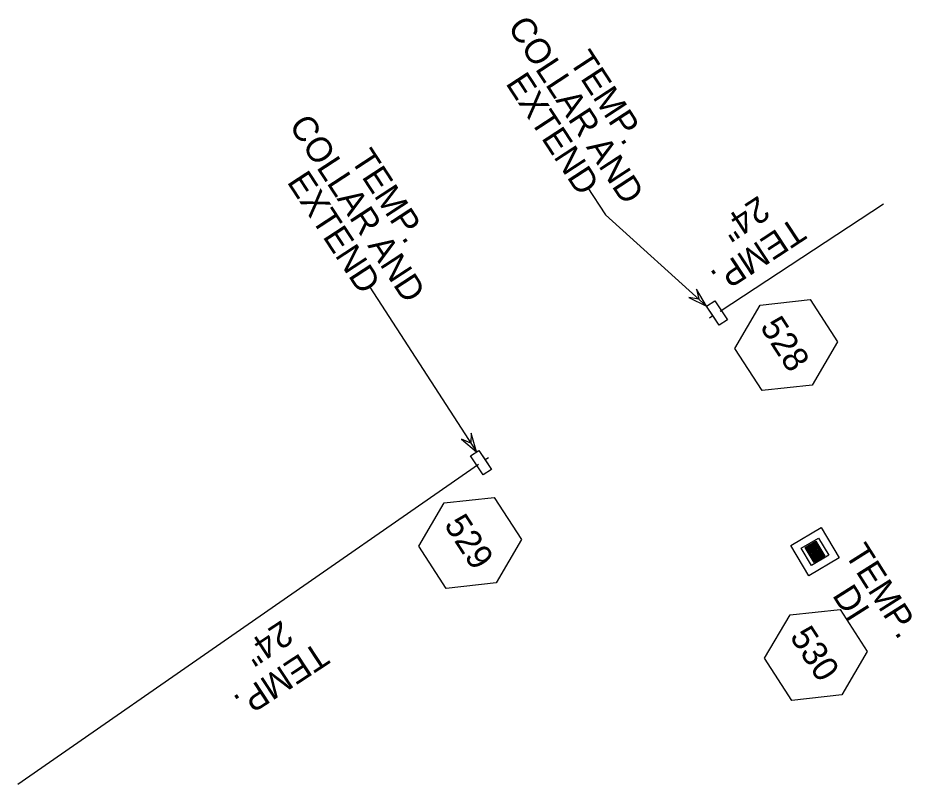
# Model space of a CAD drawing. Extents: x 2009474 to 2011404, y 538919 to 548212.
# Drawn here: x 2009473.8 to 2009651.7, y 548059.9 to 548212.4 of the extents above; entities that cross this region are included whole.
import ezdxf

# ---------------------------------------------------------------- set-up
doc = ezdxf.new("R2010")
doc.units = 0
for name, color, linetype in [('Prop Drainage Structure Box Number Symbol CELL', 7, 'Continuous'), ('Prop Drainage Structure Drop Inlet Grate 840 16 CELL', 7, 'Continuous'), ('Prop Drainage Structure Drop Inlet Grate 840 16 Label', 7, 'Continuous'), ('Prop Drainage Structure Pipe Alternate 24in', 7, 'Continuous'), ('Prop Drainage Structure Pipe Alternate 24in Label', 7, 'Continuous'), ('Prop Drainage Structure Pipe Collar CELL', 7, 'Continuous'), ('Prop Drainage Structure Pipe Collar Label', 7, 'Continuous'), ('Prop Drainage Structure Plot Symbol 20 Scale', 7, 'Continuous'), ('Prop Drainage Structure Plot Symbol 50 Scale', 7, 'Continuous')]:
    doc.layers.add(name, color=color, linetype=linetype)

msp = doc.modelspace()

# ---------------------------------------------------------------- linework, layer by layer
at = {"layer": 'Prop Drainage Structure Box Number Symbol CELL'}
for points in [[(2009631.39, 548156.33), (2009636.82, 548147.93), (2009631.75, 548139.32), (2009621.81, 548138.21), (2009616.37, 548146.61), (2009621.45, 548155.22), (2009631.39, 548156.33)], [(2009568.52, 548116.97), (2009573.95, 548108.58), (2009568.88, 548099.96), (2009558.94, 548098.86), (2009553.5, 548107.25), (2009558.58, 548115.87), (2009568.52, 548116.97)], [(2009637.31, 548094.67), (2009642.74, 548086.28), (2009637.67, 548077.66), (2009627.73, 548076.55), (2009622.29, 548084.95), (2009627.37, 548093.56), (2009637.31, 548094.67)]]:
    msp.add_lwpolyline(points, dxfattribs=at)
at = {"layer": 'Prop Drainage Structure Drop Inlet Grate 840 16 CELL'}
for p, q in [((2009631.44, 548107.64), (2009631.44, 548107.64)), ((2009631.26, 548105.5), (2009631.26, 548105.5)), ((2009632.33, 548106.14), (2009632.33, 548106.14)), ((2009633.4, 548106.78), (2009633.4, 548106.78)), ((2009633.23, 548104.64), (2009633.23, 548104.64))]:
    msp.add_line(p, q, dxfattribs=at)
for points in [[(2009632.51, 548108.28), (2009634.3, 548105.28), (2009632.15, 548104), (2009630.36, 548107), (2009630.36, 548107), (2009632.51, 548108.28)], [(2009632.48, 548108.17), (2009634.19, 548105.31), (2009632.18, 548104.11), (2009630.48, 548106.98), (2009630.48, 548106.98), (2009632.48, 548108.17)], [(2009631.34, 548105.55), (2009633.32, 548106.73), (2009634.17, 548105.31), (2009632.19, 548104.13), (2009630.49, 548106.97), (2009632.48, 548108.16), (2009633.32, 548106.73)], [(2009631.3, 548107.3), (2009632.01, 548106.1), (2009631.87, 548106.01), (2009631.16, 548107.21), (2009631.3, 548107.3)], [(2009631.53, 548107.43), (2009632.24, 548106.23), (2009632.1, 548106.15), (2009631.38, 548107.35), (2009631.53, 548107.43)], [(2009631.76, 548107.57), (2009632.47, 548106.37), (2009632.33, 548106.28), (2009631.61, 548107.48), (2009631.76, 548107.57)], [(2009631.98, 548107.7), (2009632.7, 548106.51), (2009632.56, 548106.42), (2009631.84, 548107.62), (2009631.98, 548107.7)], [(2009632.21, 548107.84), (2009632.93, 548106.64), (2009632.78, 548106.56), (2009632.07, 548107.76), (2009632.21, 548107.84)], [(2009632.44, 548107.98), (2009633.16, 548106.78), (2009633.01, 548106.69), (2009632.3, 548107.89), (2009632.44, 548107.98)], [(2009630.84, 548107.02), (2009631.56, 548105.83), (2009631.38, 548105.72), (2009630.66, 548106.92), (2009630.84, 548107.02), (2009630.84, 548107.02)], [(2009631.07, 548107.16), (2009631.79, 548105.96), (2009631.64, 548105.88), (2009630.93, 548107.08), (2009631.07, 548107.16)], [(2009631.69, 548105.61), (2009632.4, 548104.41), (2009632.22, 548104.31), (2009631.51, 548105.5), (2009631.69, 548105.61), (2009631.69, 548105.61)], [(2009631.91, 548105.75), (2009632.63, 548104.55), (2009632.49, 548104.46), (2009631.77, 548105.66), (2009631.91, 548105.75)], [(2009632.14, 548105.88), (2009632.86, 548104.68), (2009632.71, 548104.6), (2009632, 548105.8), (2009632.14, 548105.88)], [(2009632.37, 548106.02), (2009633.09, 548104.82), (2009632.94, 548104.73), (2009632.23, 548105.93), (2009632.37, 548106.02)], [(2009632.6, 548106.15), (2009633.31, 548104.96), (2009633.17, 548104.87), (2009632.46, 548106.07), (2009632.6, 548106.15)], [(2009632.83, 548106.29), (2009633.54, 548105.09), (2009633.4, 548105.01), (2009632.68, 548106.21), (2009632.83, 548106.29)], [(2009633.06, 548106.43), (2009633.77, 548105.23), (2009633.63, 548105.14), (2009632.91, 548106.34), (2009633.06, 548106.43)], [(2009633.28, 548106.56), (2009634, 548105.36), (2009633.85, 548105.28), (2009633.14, 548106.48), (2009633.28, 548106.56)]]:
    msp.add_lwpolyline(points, dxfattribs=at)
at = {"layer": 'Prop Drainage Structure Pipe Alternate 24in'}
for p, q in [((2009645.96, 548175.33), (2009613.44, 548153.96)), ((2009473.76, 548059.89), (2009565.39, 548123.61))]:
    msp.add_line(p, q, dxfattribs=at)
at = {"layer": 'Prop Drainage Structure Pipe Collar CELL'}
for p, q in [((2009612.02, 548153.14), (2009612.02, 548153.14)), ((2009612.02, 548153.14), (2009612.02, 548153.14)), ((2009566.72, 548124.41), (2009566.72, 548124.41)), ((2009566.72, 548124.41), (2009566.72, 548124.41))]:
    msp.add_line(p, q, dxfattribs=at)
for points in [[(2009610.77, 548155.04), (2009612.43, 548156.12), (2009614.91, 548152.32), (2009613.26, 548151.24)], [(2009567.96, 548122.51), (2009566.3, 548121.43), (2009563.82, 548125.23), (2009565.47, 548126.31)]]:
    msp.add_lwpolyline(points, close=True, dxfattribs=at)
for points in [[(2009611.37, 548152.72), (2009612.02, 548153.14), (2009610.77, 548155.04), (2009612.43, 548156.12), (2009614.91, 548152.32), (2009613.26, 548151.24), (2009613.26, 548151.24), (2009612.02, 548153.14)], [(2009567.36, 548124.83), (2009566.72, 548124.41), (2009567.96, 548122.51), (2009566.3, 548121.43), (2009563.82, 548125.23), (2009565.47, 548126.31), (2009565.47, 548126.31), (2009566.72, 548124.41)]]:
    msp.add_lwpolyline(points, dxfattribs=at)
at = {"layer": 'Prop Drainage Structure Pipe Collar Label'}
for p, q in [((2009587, 548178.81), (2009590.63, 548173.21)), ((2009590.63, 548173.21), (2009610.77, 548155.04)), ((2009543.8, 548158.78), (2009565.01, 548126.01))]:
    msp.add_line(p, q, dxfattribs=at)
for points in [[(2009610.77, 548155.04), (2009608.74, 548158.39), (2009609.21, 548156.45), (2009607.23, 548156.72)], [(2009565.01, 548126.01), (2009563.92, 548129.78), (2009563.87, 548127.78), (2009562.02, 548128.55)]]:
    msp.add_lwpolyline(points, close=True, dxfattribs=at)
at = {"layer": 'Prop Drainage Structure Plot Symbol 20 Scale'}
msp.add_lwpolyline([(2009633.02, 548108.88), (2009635.07, 548105.45), (2009631.64, 548103.4), (2009629.59, 548106.83)], close=True, dxfattribs=at)
at = {"layer": 'Prop Drainage Structure Plot Symbol 50 Scale'}
msp.add_lwpolyline([(2009633.55, 548110.94), (2009637.13, 548104.93), (2009631.12, 548101.34), (2009627.53, 548107.36)], close=True, dxfattribs=at)

# ---------------------------------------------------------------- texts
at = {"layer": 'Prop Drainage Structure Box Number Symbol CELL'}
for s, p in [('528', (2009621.27, 548150.9)), ('529', (2009558.42, 548111.52)), ('530', (2009627.19, 548089.25))]:
    msp.add_text(s, height=5, rotation=302.919, dxfattribs=at).set_placement(p)
at = {"layer": 'Prop Drainage Structure Drop Inlet Grate 840 16 Label'}
for s, p in [('TEMP.', (2009638.14, 548105.71)), ('DI', (2009635.65, 548097.49))]:
    msp.add_text(s, height=5, rotation=302.3213, dxfattribs=at).set_placement(p)
at = {"layer": 'Prop Drainage Structure Pipe Alternate 24in Label'}
for s, p in [('24"', (2009621.13, 548177.15)), ('TEMP.', (2009628.23, 548172.84)), ('24"', (2009526.28, 548092.65)), ('TEMP.', (2009533.38, 548088.33))]:
    msp.add_text(s, height=5, rotation=213.295, dxfattribs=at).set_placement(p)
at = {"layer": 'Prop Drainage Structure Pipe Collar Label'}
for s, p in [('COLLAR AND', (2009571.06, 548210.66)), ('TEMP.', (2009583.31, 548203.8)), ('EXTEND', (2009570.67, 548199.38)), ('COLLAR AND', (2009527.56, 548191.05)), ('TEMP.', (2009539.81, 548184.19)), ('EXTEND', (2009527.17, 548179.76))]:
    msp.add_text(s, height=5, rotation=303.1629, dxfattribs=at).set_placement(p)

doc.saveas('drawing.dxf')
